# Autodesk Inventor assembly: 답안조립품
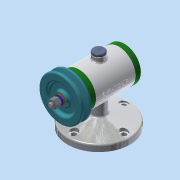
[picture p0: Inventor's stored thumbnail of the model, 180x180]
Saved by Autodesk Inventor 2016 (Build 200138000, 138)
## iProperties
Created: 2018-12
Part Number: 답안조립품
Material: 일반
Document SubType Name: Assembly
Designer: 3sil_cad0123
Author: 3sil_cad0123
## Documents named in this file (15)
- C:\Users\3sil_cad0123\Desktop\481207V1010\답안조립품.iam
- C:\Users\3sil_cad0123\Desktop\481207V1010\본체.ipt
- C:\Users\3sil_cad0123\Desktop\481207V1010\V벨트풀리.ipt
- C:\Users\3sil_cad0123\Desktop\481207V1010\고무캡.ipt
- C:\Users\3sil_cad0123\Desktop\481207V1010\너트 M8.ipt
- 너트 M8.ipt
- C:\Users\3sil_cad0123\Desktop\481207V1010\뒤커버.ipt
- C:\Users\3sil_cad0123\Desktop\481207V1010\베어링 15 x 32 x 9.ipt
- C:\Users\3sil_cad0123\Desktop\481207V1010\볼트 M4 x 12.ipt
- C:\Users\3sil_cad0123\Desktop\481207V1010\스프링와셔 8.ipt
- C:\Users\3sil_cad0123\Desktop\481207V1010\앞커버.ipt
- C:\Users\3sil_cad0123\Desktop\481207V1010\오일 실 15 25 7.ipt
- C:\Users\3sil_cad0123\Desktop\481207V1010\와셔 8x17.ipt
- C:\Users\3sil_cad0123\Desktop\481207V1010\축.ipt
- C:\Users\3sil_cad0123\Desktop\481207V1010\키 3 x 3 x 12.ipt
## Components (2 placed, 2 different names)
1. V벨트풀리:1 — 각도:2
2. 고무캡:1 — 각도:3
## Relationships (2: Angle 2)
- 각도:2 [Angle]: V벨트풀리:1
- 각도:3 [Angle]: 고무캡:1
